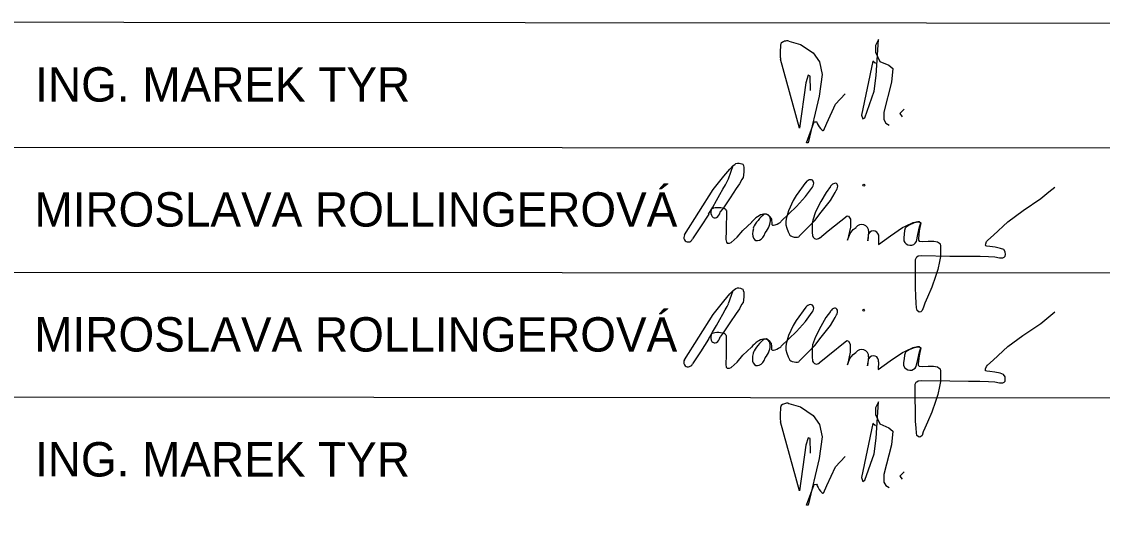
# Model space of a CAD drawing. Extents: x -467927 to -455912, y -1105662 to -1104439.
# Drawn here: x -458626.9 to -458564.6, y -1105013.2 to -1104984.8 of the extents above; entities that cross this region are included whole.
import ezdxf

# ---------------------------------------------------------------- set-up
doc = ezdxf.new("R2010")
doc.units = 0
doc.layers.add('Implicitní', color=7, linetype='Continuous')
doc.layers.add('Rozpiska TMS', color=7, linetype='Continuous')

msp = doc.modelspace()

# ---------------------------------------------------------------- linework, layer by layer
at = {"layer": 'Implicitní'}
for p, q in [((-458667.313, -1104992.041), (-458562.274, -1104992.119)), ((-458585.706, -1104993.013), (-458585.61, -1104992.989)), ((-458585.61, -1104992.989), (-458585.53, -1104992.989)), ((-458585.53, -1104992.989), (-458585.435, -1104993.007)), ((-458586.403, -1104993.744), (-458586.055, -1104993.334)), ((-458586.127, -1104993.891), (-458585.863, -1104993.132)), ((-458586.055, -1104993.334), (-458585.863, -1104993.139)), ((-458585.863, -1104993.139), (-458585.777, -1104993.067)), ((-458585.777, -1104993.067), (-458585.706, -1104993.013)), ((-458585.435, -1104993.007), (-458585.37, -1104993.03)), ((-458585.37, -1104993.03), (-458585.314, -1104993.054)), ((-458585.314, -1104993.054), (-458585.28, -1104993.128)), ((-458585.28, -1104993.128), (-458585.25, -1104993.239)), ((-458585.25, -1104993.477), (-458585.266, -1104993.692)), ((-458585.25, -1104993.239), (-458585.25, -1104993.477)), ((-458587.016, -1104994.516), (-458586.403, -1104993.744)), ((-458585.505, -1104994.182), (-458585.687, -1104994.456)), ((-458585.371, -1104993.947), (-458585.505, -1104994.182)), ((-458585.284, -1104993.816), (-458585.371, -1104993.947)), ((-458585.266, -1104993.692), (-458585.284, -1104993.816)), ((-458581.67, -1104994.097), (-458582.237, -1104994.86)), ((-458588.669, -1104997.121), (-458587.016, -1104994.516)), ((-458585.687, -1104994.456), (-458586.047, -1104994.998)), ((-458582.237, -1104994.86), (-458582.404, -1104995.157)), ((-458581.693, -1104994.919), (-458581.301, -1104994.387)), ((-458580.512, -1104994.694), (-458580.805, -1104995.206)), ((-458580.244, -1104994.334), (-458580.512, -1104994.694)), ((-458580.257, -1104995.15), (-458579.985, -1104994.691)), ((-458579.985, -1104994.691), (-458579.905, -1104994.539)), ((-458568.113, -1104995.027), (-458567.66, -1104994.642)), ((-458567.66, -1104994.642), (-458567.319, -1104994.37)), ((-458586.047, -1104994.998), (-458586.43, -1104995.574)), ((-458583.097, -1104996.341), (-458582.209, -1104995.496)), ((-458582.404, -1104995.157), (-458582.67, -1104995.735)), ((-458582.209, -1104995.496), (-458581.693, -1104994.919)), ((-458580.805, -1104995.206), (-458581.113, -1104995.805)), ((-458580.786, -1104995.825), (-458580.257, -1104995.15)), ((-458569.146, -1104995.732), (-458568.113, -1104995.027)), ((-458587.278, -1104995.942), (-458587.745, -1104996.667)), ((-458586.43, -1104995.574), (-458586.61, -1104995.808)), ((-458586.257, -1104995.719), (-458586.273, -1104996.869)), ((-458582.67, -1104995.735), (-458582.804, -1104996.198)), ((-458581.113, -1104995.805), (-458581.281, -1104996.273)), ((-458581.156, -1104996.303), (-458580.786, -1104995.825)), ((-458580.394, -1104996.89), (-458579.301, -1104996.024)), ((-458579.301, -1104996.024), (-458579.217, -1104996.048)), ((-458579.217, -1104996.048), (-458579.108, -1104996.217)), ((-458570.019, -1104996.368), (-458569.146, -1104995.732)), ((-458587.745, -1104996.667), (-458588.209, -1104997.364)), ((-458585.3, -1104996.869), (-458584.799, -1104996.398)), ((-458582.804, -1104996.198), (-458582.821, -1104996.371)), ((-458582.821, -1104996.371), (-458582.821, -1104996.556)), ((-458582.821, -1104996.556), (-458582.771, -1104996.748)), ((-458582.058, -1104997.211), (-458581.156, -1104996.303)), ((-458581.31, -1104996.46), (-458581.311, -1104996.944)), ((-458581.281, -1104996.273), (-458581.31, -1104996.46)), ((-458579.108, -1104996.693), (-458579.276, -1104997.426)), ((-458579.108, -1104996.217), (-458579.108, -1104996.693)), ((-458578.939, -1104996.826), (-458578.782, -1104996.711)), ((-458576.799, -1104997.186), (-458576.098, -1104996.703)), ((-458576.098, -1104996.703), (-458575.93, -1104996.632)), ((-458575.95, -1104996.74), (-458575.986, -1104996.867)), ((-458575.893, -1104996.676), (-458575.95, -1104996.74)), ((-458575.93, -1104996.632), (-458575.477, -1104996.422)), ((-458575.712, -1104996.561), (-458575.893, -1104996.676)), ((-458575.424, -1104996.443), (-458575.712, -1104996.561)), ((-458575.477, -1104996.422), (-458575.224, -1104996.359)), ((-458575.186, -1104996.394), (-458575.424, -1104996.443)), ((-458575.224, -1104996.359), (-458575.137, -1104996.364)), ((-458575.21, -1104997.105), (-458575.123, -1104996.667)), ((-458575.038, -1104996.443), (-458575.186, -1104996.394)), ((-458575.137, -1104996.364), (-458575.038, -1104996.443)), ((-458575.038, -1104996.443), (-458575.135, -1104996.894)), ((-458575.123, -1104996.667), (-458575.038, -1104996.443)), ((-458570.857, -1104997.142), (-458570.019, -1104996.368)), ((-458586.273, -1104996.869), (-458586.284, -1104997.395)), ((-458585.979, -1104997.571), (-458585.636, -1104997.255)), ((-458585.636, -1104997.255), (-458585.3, -1104996.869)), ((-458582.771, -1104996.748), (-458582.695, -1104996.961)), ((-458582.695, -1104996.961), (-458582.618, -1104997.108)), ((-458581.311, -1104996.944), (-458581.282, -1104997.212)), ((-458580.893, -1104997.31), (-458580.394, -1104996.89)), ((-458579.276, -1104997.426), (-458579.126, -1104997.043)), ((-458579.126, -1104997.043), (-458578.939, -1104996.826)), ((-458578.057, -1104996.956), (-458578.107, -1104997.476)), ((-458578.107, -1104997.476), (-458578.045, -1104997.054)), ((-458577.491, -1104997.69), (-458576.799, -1104997.186)), ((-458577.476, -1104997.249), (-458577.491, -1104997.69)), ((-458576.007, -1104997.079), (-458576.032, -1104997.291)), ((-458576.032, -1104997.291), (-458576.032, -1104997.466)), ((-458575.986, -1104996.867), (-458576.007, -1104997.079)), ((-458575.299, -1104997.505), (-458575.21, -1104997.105)), ((-458575.135, -1104996.894), (-458575.187, -1104997.346)), ((-458575.187, -1104997.346), (-458575.187, -1104997.429)), ((-458571.185, -1104997.432), (-458570.857, -1104997.142)), ((-458586.284, -1104997.395), (-458586.258, -1104997.557)), ((-458586.258, -1104997.557), (-458586.206, -1104997.613)), ((-458586.206, -1104997.613), (-458586.081, -1104997.613)), ((-458586.081, -1104997.613), (-458585.979, -1104997.571)), ((-458575.187, -1104997.429), (-458575.138, -1104997.486)), ((-458575.138, -1104997.486), (-458574.944, -1104997.505)), ((-458574.944, -1104997.505), (-458574.616, -1104997.49)), ((-458574.616, -1104997.49), (-458574.3, -1104997.49)), ((-458574.3, -1104997.49), (-458574.081, -1104997.533)), ((-458574.081, -1104997.533), (-458573.974, -1104997.603)), ((-458573.974, -1104997.603), (-458573.928, -1104997.654)), ((-458573.928, -1104997.654), (-458573.908, -1104997.787)), ((-458573.908, -1104997.787), (-458573.908, -1104998.068)), ((-458571.308, -1104997.72), (-458571.3, -1104997.64)), ((-458571.3, -1104997.754), (-458571.308, -1104997.72)), ((-458571.3, -1104997.64), (-458571.253, -1104997.508)), ((-458571.228, -1104997.78), (-458571.3, -1104997.754)), ((-458571.253, -1104997.508), (-458571.185, -1104997.432)), ((-458571.06, -1104997.798), (-458571.228, -1104997.78)), ((-458570.761, -1104997.832), (-458571.06, -1104997.798)), ((-458570.454, -1104997.905), (-458570.761, -1104997.832)), ((-458570.262, -1104997.975), (-458570.454, -1104997.905)), ((-458570.171, -1104998.113), (-458570.262, -1104997.975)), ((-458575.36, -1104998.538), (-458575.3, -1104998.424)), ((-458575.36, -1104998.719), (-458575.36, -1104998.538)), ((-458575.3, -1104998.424), (-458575.265, -1104998.389)), ((-458575.265, -1104998.389), (-458575.188, -1104998.337)), ((-458575.188, -1104998.337), (-458575.004, -1104998.311)), ((-458575.004, -1104998.311), (-458573.369, -1104998.347)), ((-458573.909, -1104998.377), (-458573.96, -1104998.664)), ((-458573.908, -1104998.068), (-458573.909, -1104998.377)), ((-458573.369, -1104998.347), (-458572.284, -1104998.353)), ((-458572.284, -1104998.353), (-458571.629, -1104998.354)), ((-458571.629, -1104998.354), (-458571.139, -1104998.375)), ((-458571.139, -1104998.375), (-458570.78, -1104998.401)), ((-458570.78, -1104998.401), (-458570.507, -1104998.448)), ((-458570.507, -1104998.448), (-458570.395, -1104998.453)), ((-458570.395, -1104998.453), (-458570.314, -1104998.453)), ((-458570.314, -1104998.453), (-458570.237, -1104998.422)), ((-458570.237, -1104998.422), (-458570.172, -1104998.355)), ((-458570.172, -1104998.355), (-458570.166, -1104998.258)), ((-458570.166, -1104998.258), (-458570.171, -1104998.113)), ((-458575.36, -1104999.215), (-458575.36, -1104998.719)), ((-458575.347, -1105000.157), (-458575.36, -1104999.215)), ((-458574.058, -1104999.127), (-458574.192, -1104999.523)), ((-458573.96, -1104998.664), (-458574.058, -1104999.127)), ((-458667.318, -1104999.241), (-458562.279, -1104999.319)), ((-458574.192, -1104999.523), (-458574.411, -1105000.142)), ((-458586.133, -1105001.091), (-458585.868, -1105000.332)), ((-458586.06, -1105000.534), (-458585.868, -1105000.339)), ((-458585.868, -1105000.339), (-458585.782, -1105000.267)), ((-458585.782, -1105000.267), (-458585.711, -1105000.213)), ((-458585.711, -1105000.213), (-458585.615, -1105000.189)), ((-458585.615, -1105000.189), (-458585.535, -1105000.189)), ((-458585.535, -1105000.189), (-458585.44, -1105000.207)), ((-458585.44, -1105000.207), (-458585.375, -1105000.23)), ((-458585.375, -1105000.23), (-458585.319, -1105000.254)), ((-458585.319, -1105000.254), (-458585.285, -1105000.328)), ((-458585.285, -1105000.328), (-458585.255, -1105000.439)), ((-458585.255, -1105000.439), (-458585.255, -1105000.677)), ((-458575.337, -1105000.664), (-458575.347, -1105000.157)), ((-458574.411, -1105000.142), (-458574.662, -1105000.722)), ((-458587.021, -1105001.716), (-458586.408, -1105000.944)), ((-458586.408, -1105000.944), (-458586.06, -1105000.534)), ((-458585.29, -1105001.016), (-458585.377, -1105001.147)), ((-458585.271, -1105000.892), (-458585.29, -1105001.016)), ((-458585.255, -1105000.677), (-458585.271, -1105000.892)), ((-458575.314, -1105001.063), (-458575.337, -1105000.664)), ((-458575.291, -1105001.335), (-458575.314, -1105001.063)), ((-458574.814, -1105001.073), (-458574.896, -1105001.286)), ((-458574.662, -1105000.722), (-458574.814, -1105001.073)), ((-458588.674, -1105004.321), (-458587.021, -1105001.716)), ((-458585.692, -1105001.656), (-458586.052, -1105002.198)), ((-458585.511, -1105001.382), (-458585.692, -1105001.656)), ((-458585.377, -1105001.147), (-458585.511, -1105001.382)), ((-458581.676, -1105001.297), (-458582.242, -1105002.06)), ((-458581.698, -1105002.119), (-458581.306, -1105001.587)), ((-458580.249, -1105001.534), (-458580.517, -1105001.894)), ((-458575.26, -1105001.489), (-458575.291, -1105001.335)), ((-458575.139, -1105001.578), (-458575.26, -1105001.489)), ((-458575.052, -1105001.559), (-458575.139, -1105001.578)), ((-458574.97, -1105001.489), (-458575.052, -1105001.559)), ((-458574.896, -1105001.286), (-458574.97, -1105001.489)), ((-458567.665, -1105001.842), (-458567.324, -1105001.57)), ((-458586.052, -1105002.198), (-458586.435, -1105002.774)), ((-458582.242, -1105002.06), (-458582.41, -1105002.357)), ((-458582.215, -1105002.696), (-458581.698, -1105002.119)), ((-458580.517, -1105001.894), (-458580.811, -1105002.406)), ((-458580.791, -1105003.025), (-458580.262, -1105002.35)), ((-458580.262, -1105002.35), (-458579.99, -1105001.891)), ((-458579.99, -1105001.891), (-458579.91, -1105001.739)), ((-458569.151, -1105002.932), (-458568.118, -1105002.227)), ((-458568.118, -1105002.227), (-458567.665, -1105001.842)), ((-458586.435, -1105002.774), (-458586.615, -1105003.008)), ((-458586.262, -1105002.919), (-458586.279, -1105004.069)), ((-458583.102, -1105003.541), (-458582.215, -1105002.696)), ((-458582.675, -1105002.935), (-458582.809, -1105003.398)), ((-458582.41, -1105002.357), (-458582.675, -1105002.935)), ((-458580.811, -1105002.406), (-458581.118, -1105003.005)), ((-458570.024, -1105003.568), (-458569.151, -1105002.932)), ((-458587.283, -1105003.142), (-458587.751, -1105003.867)), ((-458585.306, -1105004.069), (-458584.804, -1105003.598)), ((-458582.826, -1105003.571), (-458582.827, -1105003.756)), ((-458582.809, -1105003.398), (-458582.826, -1105003.571)), ((-458582.063, -1105004.411), (-458581.161, -1105003.503)), ((-458581.286, -1105003.473), (-458581.315, -1105003.66)), ((-458581.118, -1105003.005), (-458581.286, -1105003.473)), ((-458581.161, -1105003.503), (-458580.791, -1105003.025)), ((-458580.4, -1105004.09), (-458579.306, -1105003.224)), ((-458579.306, -1105003.224), (-458579.222, -1105003.248)), ((-458579.222, -1105003.248), (-458579.113, -1105003.417)), ((-458579.113, -1105003.417), (-458579.114, -1105003.893)), ((-458575.482, -1105003.622), (-458575.229, -1105003.559)), ((-458575.191, -1105003.594), (-458575.429, -1105003.643)), ((-458575.229, -1105003.559), (-458575.142, -1105003.564)), ((-458575.043, -1105003.643), (-458575.191, -1105003.594)), ((-458575.142, -1105003.564), (-458575.043, -1105003.643)), ((-458570.862, -1105004.342), (-458570.024, -1105003.568)), ((-458587.751, -1105003.867), (-458588.214, -1105004.564)), ((-458586.279, -1105004.069), (-458586.289, -1105004.595)), ((-458585.641, -1105004.455), (-458585.306, -1105004.069)), ((-458582.827, -1105003.756), (-458582.777, -1105003.948)), ((-458582.777, -1105003.948), (-458582.7, -1105004.161)), ((-458582.7, -1105004.161), (-458582.623, -1105004.308)), ((-458581.315, -1105003.66), (-458581.316, -1105004.144)), ((-458581.316, -1105004.144), (-458581.287, -1105004.412)), ((-458580.898, -1105004.51), (-458580.4, -1105004.09)), ((-458579.114, -1105003.893), (-458579.281, -1105004.626)), ((-458579.131, -1105004.243), (-458578.945, -1105004.026)), ((-458578.945, -1105004.026), (-458578.788, -1105003.911)), ((-458578.062, -1105004.156), (-458578.112, -1105004.676)), ((-458576.804, -1105004.386), (-458576.104, -1105003.903)), ((-458576.104, -1105003.903), (-458575.936, -1105003.832)), ((-458575.992, -1105004.067), (-458576.012, -1105004.279)), ((-458575.956, -1105003.94), (-458575.992, -1105004.067)), ((-458575.899, -1105003.876), (-458575.956, -1105003.94)), ((-458575.936, -1105003.832), (-458575.482, -1105003.622)), ((-458575.718, -1105003.761), (-458575.899, -1105003.876)), ((-458575.429, -1105003.643), (-458575.718, -1105003.761)), ((-458575.215, -1105004.305), (-458575.129, -1105003.867)), ((-458575.141, -1105004.094), (-458575.192, -1105004.546)), ((-458575.043, -1105003.643), (-458575.141, -1105004.094)), ((-458575.129, -1105003.867), (-458575.043, -1105003.643)), ((-458586.289, -1105004.595), (-458586.263, -1105004.757)), ((-458586.263, -1105004.757), (-458586.211, -1105004.813)), ((-458586.211, -1105004.813), (-458586.086, -1105004.813)), ((-458586.086, -1105004.813), (-458585.984, -1105004.771)), ((-458585.984, -1105004.771), (-458585.641, -1105004.455)), ((-458579.281, -1105004.626), (-458579.131, -1105004.243)), ((-458578.112, -1105004.676), (-458578.05, -1105004.254)), ((-458577.496, -1105004.89), (-458576.804, -1105004.386)), ((-458577.481, -1105004.449), (-458577.496, -1105004.89)), ((-458576.012, -1105004.279), (-458576.037, -1105004.491)), ((-458576.037, -1105004.491), (-458576.037, -1105004.666)), ((-458575.304, -1105004.705), (-458575.215, -1105004.305)), ((-458575.192, -1105004.546), (-458575.192, -1105004.629)), ((-458575.192, -1105004.629), (-458575.143, -1105004.686)), ((-458575.143, -1105004.686), (-458574.949, -1105004.705)), ((-458574.949, -1105004.705), (-458574.621, -1105004.69)), ((-458574.621, -1105004.69), (-458574.305, -1105004.69)), ((-458574.305, -1105004.69), (-458574.086, -1105004.733)), ((-458574.086, -1105004.733), (-458573.979, -1105004.803)), ((-458573.979, -1105004.803), (-458573.933, -1105004.854)), ((-458571.313, -1105004.92), (-458571.305, -1105004.84)), ((-458571.305, -1105004.84), (-458571.258, -1105004.708)), ((-458571.258, -1105004.708), (-458571.19, -1105004.632)), ((-458571.19, -1105004.632), (-458570.862, -1105004.342)), ((-458573.933, -1105004.854), (-458573.913, -1105004.987)), ((-458573.913, -1105004.987), (-458573.914, -1105005.268)), ((-458573.914, -1105005.268), (-458573.914, -1105005.577)), ((-458571.305, -1105004.954), (-458571.313, -1105004.92)), ((-458571.233, -1105004.98), (-458571.305, -1105004.954)), ((-458571.065, -1105004.998), (-458571.233, -1105004.98)), ((-458570.766, -1105005.032), (-458571.065, -1105004.998)), ((-458570.46, -1105005.105), (-458570.766, -1105005.032)), ((-458570.268, -1105005.175), (-458570.46, -1105005.105)), ((-458570.177, -1105005.313), (-458570.268, -1105005.175)), ((-458570.172, -1105005.458), (-458570.177, -1105005.313)), ((-458570.177, -1105005.555), (-458570.172, -1105005.458)), ((-458575.365, -1105005.738), (-458575.305, -1105005.624)), ((-458575.365, -1105005.919), (-458575.365, -1105005.738)), ((-458575.365, -1105006.415), (-458575.365, -1105005.919)), ((-458575.305, -1105005.624), (-458575.27, -1105005.589)), ((-458575.27, -1105005.589), (-458575.193, -1105005.537)), ((-458575.193, -1105005.537), (-458575.009, -1105005.511)), ((-458575.009, -1105005.511), (-458573.374, -1105005.547)), ((-458573.965, -1105005.864), (-458574.063, -1105006.327)), ((-458573.914, -1105005.577), (-458573.965, -1105005.864)), ((-458573.374, -1105005.547), (-458572.289, -1105005.553)), ((-458572.289, -1105005.553), (-458571.634, -1105005.554)), ((-458571.634, -1105005.554), (-458571.144, -1105005.575)), ((-458571.144, -1105005.575), (-458570.785, -1105005.601)), ((-458570.785, -1105005.601), (-458570.512, -1105005.648)), ((-458570.512, -1105005.648), (-458570.4, -1105005.653)), ((-458570.4, -1105005.653), (-458570.319, -1105005.653)), ((-458570.319, -1105005.653), (-458570.242, -1105005.622)), ((-458570.242, -1105005.622), (-458570.177, -1105005.555)), ((-458667.323, -1105006.441), (-458562.284, -1105006.519)), ((-458575.352, -1105007.357), (-458575.365, -1105006.415)), ((-458574.063, -1105006.327), (-458574.198, -1105006.723)), ((-458574.416, -1105007.342), (-458574.668, -1105007.922)), ((-458574.198, -1105006.723), (-458574.416, -1105007.342)), ((-458575.343, -1105007.864), (-458575.352, -1105007.357)), ((-458575.319, -1105008.263), (-458575.343, -1105007.864)), ((-458574.668, -1105007.922), (-458574.819, -1105008.273)), ((-458575.296, -1105008.535), (-458575.319, -1105008.263)), ((-458575.265, -1105008.689), (-458575.296, -1105008.535)), ((-458574.901, -1105008.486), (-458574.975, -1105008.689)), ((-458574.819, -1105008.273), (-458574.901, -1105008.486)), ((-458575.144, -1105008.778), (-458575.265, -1105008.689)), ((-458575.057, -1105008.759), (-458575.144, -1105008.778)), ((-458574.975, -1105008.689), (-458575.057, -1105008.759))]:
    msp.add_line(p, q, dxfattribs=at)
msp.add_lwpolyline([(-458667.307, -1104984.841), (-458505.302, -1104984.961), (-458505.323, -1105013.762), (-458667.328, -1105013.642)], close=True, dxfattribs=at)
for centre in [(-458578.335, -1104994.266), (-458578.34, -1105001.466)]:
    msp.add_circle(centre, 0.0535, dxfattribs=at)
for centre, radius, start, end in [((-458578.451, -1104996.926), 0.4, 355.78467, 147.22874), ((-458581.053, -1104997.134), 0.238, 197.54011, 313.10888), ((-458577.777, -1104997.206), 0.309, 352.16792, 150.33963), ((-458575.657, -1104997.337), 0.394, 199.70252, 334.88277), ((-458578.457, -1105004.126), 0.4, 355.78467, 147.22874), ((-458577.782, -1105004.406), 0.309, 352.16792, 150.33963), ((-458581.058, -1105004.334), 0.238, 197.54011, 313.10888), ((-458575.662, -1105004.537), 0.394, 199.70252, 334.88277)]:
    msp.add_arc(centre, radius, start, end, dxfattribs=at)
for centre, major_axis, ratio, start_param, end_param in [((-458587.3, -1104995.932), (1.171, 2.036), 0.009505, 4.712389, 6.283185), ((-458581.486, -1104994.241), (-0.194, -0.258), 0.719657, 1.570796, 4.712389), ((-458580.072, -1104994.437), (-0.159, -0.26), 0.66672, 1.570796, 4.712389), ((-458586.874, -1104995.748), (-0.091, -0.4), 0.65459, 4.712389, 7.853982), ((-458586.701, -1104995.706), (0.435, -0.017), 0.329233, 6.283185, 9.424778), ((-458584.408, -1104996.709), (0.566, 0.719), 0.546541, 4.712389, 7.853982), ((-458584.357, -1104996.353), (0.343, 0.419), 0.173859, 0, 3.141593), ((-458583.793, -1104996.276), (-0.221, 0.341), 0.392654, 4.712389, 6.283185), ((-458583.665, -1104996.552), (0.006, 0.363), 0.109468, 4.712389, 6.283185), ((-458583.363, -1104996.447), (0.262, 0.106), 0.227956, 3.141593, 6.283185), ((-458588.438, -1104997.242), (-0.143, -0.271), 0.856584, 4.712389, 7.853982), ((-458584.357, -1104996.895), (-0.198, -0.551), 0.62126, 4.712389, 7.853982), ((-458582.334, -1104997.163), (0.279, -0.051), 0.318058, 3.141593, 6.283185), ((-458587.306, -1105003.132), (1.171, 2.036), 0.009505, 4.712389, 6.283185), ((-458581.492, -1105001.441), (-0.194, -0.258), 0.719657, 1.570796, 4.712389), ((-458580.078, -1105001.637), (-0.159, -0.26), 0.66672, 1.570796, 4.712389), ((-458586.879, -1105002.948), (-0.091, -0.4), 0.65459, 4.712389, 7.853982), ((-458586.706, -1105002.906), (0.435, -0.017), 0.329233, 6.283185, 9.424778), ((-458584.413, -1105003.909), (0.566, 0.719), 0.546541, 4.712389, 7.853982), ((-458584.362, -1105003.553), (0.343, 0.419), 0.173859, 0, 3.141593), ((-458583.798, -1105003.476), (-0.221, 0.341), 0.392654, 4.712389, 6.283185), ((-458583.67, -1105003.752), (0.006, 0.363), 0.109468, 4.712389, 6.283185), ((-458583.369, -1105003.647), (0.262, 0.106), 0.227956, 3.141593, 6.283185), ((-458584.362, -1105004.095), (-0.198, -0.551), 0.62126, 4.712389, 7.853982), ((-458588.443, -1105004.442), (-0.143, -0.271), 0.856584, 4.712389, 7.853982), ((-458582.34, -1105004.363), (0.279, -0.051), 0.318058, 3.141593, 6.283185)]:
    msp.add_ellipse(centre, major_axis=major_axis, ratio=ratio, start_param=start_param, end_param=end_param, dxfattribs=at)
at = {"layer": 'Rozpiska TMS'}
for p, q in [((-458582.663, -1104985.969), (-458581.986, -1104986.16)), ((-458577.491, -1104985.865), (-458577.665, -1104986.212)), ((-458577.614, -1104987.949), (-458577.491, -1104985.865)), ((-458581.986, -1104986.16), (-458581.257, -1104986.647)), ((-458581.257, -1104986.647), (-458580.892, -1104987.167)), ((-458577.665, -1104986.212), (-458577.665, -1104986.594)), ((-458577.665, -1104986.594), (-458577.404, -1104987.132)), ((-458582.037, -1104990.988), (-458583.131, -1104987.011)), ((-458580.892, -1104987.167), (-458580.736, -1104987.88)), ((-458577.803, -1104987.115), (-458578.462, -1104990.224)), ((-458577.665, -1104987.255), (-458577.803, -1104987.115)), ((-458577.404, -1104987.132), (-458576.884, -1104987.359)), ((-458576.884, -1104987.359), (-458576.658, -1104987.55)), ((-458581.534, -1104987.931), (-458581.673, -1104988.365)), ((-458581.43, -1104987.984), (-458581.534, -1104987.931)), ((-458581.412, -1104988.817), (-458581.43, -1104987.984)), ((-458580.736, -1104987.88), (-458580.909, -1104989.131)), ((-458577.734, -1104988.851), (-458577.614, -1104987.949)), ((-458576.658, -1104987.55), (-458576.727, -1104988.331)), ((-458581.673, -1104988.365), (-458582.037, -1104990.988)), ((-458576.727, -1104988.331), (-458577.178, -1104990.051)), ((-458580.909, -1104989.131), (-458581.551, -1104991.822)), ((-458579.972, -1104989.599), (-458579.4, -1104989.009)), ((-458578.272, -1104990.38), (-458577.734, -1104988.851)), ((-458580.458, -1104990.694), (-458579.972, -1104989.599)), ((-458578.462, -1104990.224), (-458578.394, -1104990.45)), ((-458578.394, -1104990.45), (-458578.272, -1104990.38)), ((-458577.178, -1104990.051), (-458577.178, -1104990.485)), ((-458577.178, -1104990.485), (-458577.057, -1104990.694)), ((-458575.998, -1104989.894), (-458576.258, -1104990.137)), ((-458576.258, -1104990.137), (-458576.121, -1104990.328)), ((-458581.638, -1104991.822), (-458581.187, -1104990.623)), ((-458581.187, -1104990.623), (-458581.031, -1104990.607)), ((-458580.666, -1104991.127), (-458580.458, -1104990.694)), ((-458577.057, -1104990.694), (-458576.867, -1104990.798)), ((-458581.551, -1104991.822), (-458581.638, -1104991.822)), ((-458582.663, -1105006.854), (-458581.986, -1105007.046)), ((-458581.986, -1105007.046), (-458581.257, -1105007.533)), ((-458577.491, -1105006.751), (-458577.665, -1105007.098)), ((-458577.665, -1105007.098), (-458577.665, -1105007.48)), ((-458577.614, -1105008.834), (-458577.491, -1105006.751)), ((-458582.037, -1105011.874), (-458583.131, -1105007.897)), ((-458581.257, -1105007.533), (-458580.892, -1105008.053)), ((-458577.665, -1105007.48), (-458577.404, -1105008.018)), ((-458580.892, -1105008.053), (-458580.736, -1105008.766)), ((-458577.803, -1105008.001), (-458578.462, -1105011.11)), ((-458577.665, -1105008.141), (-458577.803, -1105008.001)), ((-458577.404, -1105008.018), (-458576.884, -1105008.245)), ((-458576.884, -1105008.245), (-458576.658, -1105008.436)), ((-458576.658, -1105008.436), (-458576.727, -1105009.217)), ((-458581.534, -1105008.817), (-458581.673, -1105009.251)), ((-458581.43, -1105008.87), (-458581.534, -1105008.817)), ((-458581.412, -1105009.703), (-458581.43, -1105008.87)), ((-458580.736, -1105008.766), (-458580.909, -1105010.017)), ((-458577.734, -1105009.737), (-458577.614, -1105008.834)), ((-458581.673, -1105009.251), (-458582.037, -1105011.874)), ((-458578.272, -1105011.266), (-458577.734, -1105009.737)), ((-458576.727, -1105009.217), (-458577.178, -1105010.937)), ((-458580.909, -1105010.017), (-458581.551, -1105012.708)), ((-458579.972, -1105010.485), (-458579.4, -1105009.895)), ((-458580.458, -1105011.579), (-458579.972, -1105010.485)), ((-458577.178, -1105010.937), (-458577.178, -1105011.371)), ((-458575.998, -1105010.78), (-458576.258, -1105011.023)), ((-458576.258, -1105011.023), (-458576.121, -1105011.214)), ((-458581.638, -1105012.708), (-458581.187, -1105011.509)), ((-458581.187, -1105011.509), (-458581.031, -1105011.493)), ((-458580.666, -1105012.013), (-458580.458, -1105011.579)), ((-458578.462, -1105011.11), (-458578.394, -1105011.336)), ((-458578.394, -1105011.336), (-458578.272, -1105011.266)), ((-458577.178, -1105011.371), (-458577.057, -1105011.579)), ((-458577.057, -1105011.579), (-458576.867, -1105011.684)), ((-458581.551, -1105012.708), (-458581.638, -1105012.708))]:
    msp.add_line(p, q, dxfattribs=at)
for centre, major_axis, ratio, start_param, end_param in [((-458583.122, -1104986.568), (0.009, 0.443), 0.064441, 0, 3.141593), ((-458582.888, -1104986.047), (0.226, 0.078), 0.314219, 0, 3.141593), ((-458580.849, -1104990.867), (0.182, -0.26), 0.219584, 3.141593, 6.283185), ((-458583.122, -1105007.454), (0.009, 0.443), 0.064441, 0, 3.141593), ((-458582.888, -1105006.933), (0.226, 0.078), 0.314219, 0, 3.141593), ((-458580.849, -1105011.753), (0.182, -0.26), 0.219584, 3.141593, 6.283185)]:
    msp.add_ellipse(centre, major_axis=major_axis, ratio=ratio, start_param=start_param, end_param=end_param, dxfattribs=at)

# ---------------------------------------------------------------- texts
at = {"layer": 'Implicitní'}
for s, p in [('ING. MAREK TYR', (-458626.119, -1104989.449)), ('MIROSLAVA ROLLINGEROVÁ', (-458626.166, -1104996.649)), ('MIROSLAVA ROLLINGEROVÁ', (-458626.172, -1105003.849)), ('ING. MAREK TYR', (-458626.134, -1105011.05))]:
    msp.add_text(s, height=1.98, rotation=359.9912, dxfattribs=at).set_placement(p)

doc.saveas('drawing.dxf')
